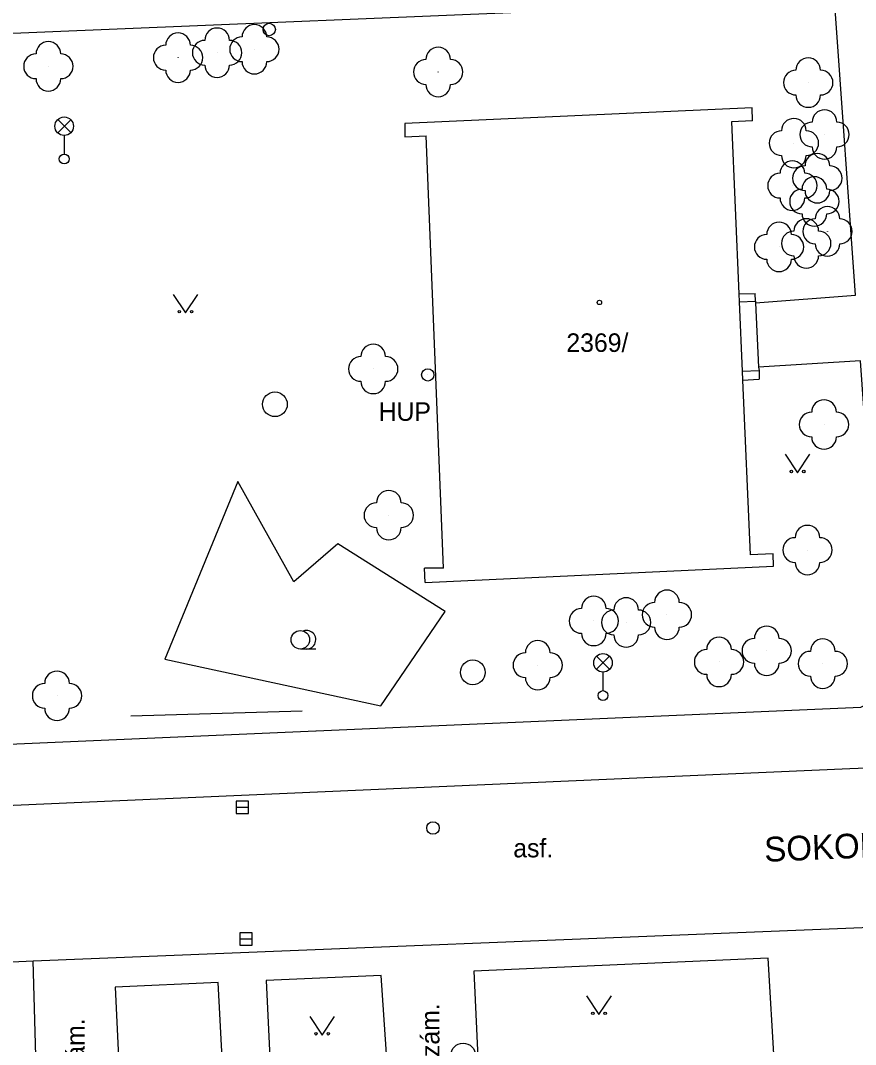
# Model space of a CAD drawing. Extents: x -737812 to -729375, y -1123000 to -1115500.
# Drawn here: x -736536.53 to -736502.72, y -1118316.28 to -1118274.83 of the extents above; entities that cross this region are included whole.
import ezdxf

# ---------------------------------------------------------------- set-up
doc = ezdxf.new("R2010")
doc.units = 0
for name, color, linetype in [('Doplněk polohopisu', 7, 'Continuous'), ('Hranice - ploty_ zdi', 7, 'Continuous'), ('Komunikace', 7, 'Continuous'), ('Názvy ulic_ silnic_ žel_', 7, 'Continuous'), ('Pomocné popisy', 7, 'Continuous'), ('Popisy povr_ zn_ inž_ sítí', 7, 'Continuous'), ('Povr_ zn_ inž_ sítí - el_', 7, 'Continuous'), ('Povr_ zn_ inž_ sítí - kan_', 7, 'Continuous'), ('Povr_ zn_ inž_ sítí - pl_', 7, 'Continuous'), ('Povr_ zn_ inž_ sítí - vod_', 7, 'Continuous'), ('Stavební objekty', 7, 'Continuous'), ('Zeleň', 7, 'Continuous'), ('Značky druhů budov', 7, 'Continuous'), ('Značky druhů pozemků', 7, 'Continuous'), ('Čísla popisná', 7, 'Continuous')]:
    doc.layers.add(name, color=color, linetype=linetype)

msp = doc.modelspace()

# ---------------------------------------------------------------- linework, layer by layer
at = {"layer": 'Doplněk polohopisu'}
for points in [[(-736506.77, -1118286.27), (-736502.73, -1118285.96), (-736503.55, -1118274.38), (-736504, -1118273.98), (-736544.99, -1118275.7), (-736552.63, -1118299.34), (-736546.81, -1118299.16), (-736546.64, -1118304.55)], [(-736546.64, -1118304.55), (-736502.51, -1118302.63), (-736501.87, -1118302.33), (-736501.61, -1118301.65), (-736502.53, -1118288.61), (-736506.65, -1118288.87)], [(-736506.01, -1118317.13), (-736506.26, -1118312.79), (-736518.18, -1118313.31), (-736517.95, -1118318.27)], [(-736528.26, -1118318.86), (-736528.53, -1118313.78), (-736532.69, -1118313.96), (-736532.45, -1118319.06)], [(-736521.62, -1118318.06), (-736521.93, -1118313.49), (-736526.58, -1118313.69), (-736526.34, -1118318.8)]]:
    msp.add_lwpolyline(points, dxfattribs=at)
at = {"layer": 'Hranice - ploty_ zdi'}
for points in [[(-736507.45, -1118285.9), (-736506.79, -1118285.88)], [(-736506.78, -1118286.19), (-736506.79, -1118285.88)], [(-736507.43, -1118286.22), (-736506.78, -1118286.19)], [(-736506.78, -1118286.19), (-736506.77, -1118286.27), (-736506.65, -1118288.87), (-736506.62, -1118289)], [(-736507.31, -1118289.03), (-736506.62, -1118289)], [(-736506.62, -1118289), (-736506.62, -1118289.36)], [(-736507.3, -1118289.39), (-736506.62, -1118289.36)], [(-736525.13, -1118302.79), (-736532.06, -1118303)]]:
    msp.add_lwpolyline(points, dxfattribs=at)
at = {"layer": 'Komunikace'}
for p, q in [((-736536.01, -1118312.9), (-736497.19, -1118311.34)), ((-736591.32, -1118315.35), (-736536.01, -1118312.9)), ((-736535.87, -1118318.46), (-736536.01, -1118312.9))]:
    msp.add_line(p, q, dxfattribs=at)
msp.add_lwpolyline([(-736400.68, -1118302.12), (-736401.85, -1118302.4), (-736402.74, -1118302.47), (-736405.69, -1118302.21), (-736408.34, -1118301.03), (-736412.01, -1118301.15), (-736413.02, -1118301.2), (-736429.04, -1118301.88), (-736430.04, -1118301.95), (-736442.01, -1118302.44), (-736443.03, -1118302.52), (-736478.54, -1118303.97), (-736491.96, -1118304.63), (-736492.94, -1118304.71), (-736501.96, -1118305.09), (-736502.96, -1118305.13), (-736535.58, -1118306.56), (-736558.89, -1118307.58), (-736559.87, -1118307.64), (-736568.86, -1118308.05), (-736569.85, -1118308.09), (-736600.81, -1118309.42)], dxfattribs=at)
at = {"layer": 'Povr_ zn_ inž_ sítí - el_'}
for p, q in [((-736535.024, -1118279.378), (-736534.496, -1118278.85)), ((-736534.488, -1118279.375), (-736535.016, -1118278.846)), ((-736534.76, -1118279.49), (-736534.76, -1118280.24)), ((-736513.214, -1118301.098), (-736512.686, -1118300.57)), ((-736512.678, -1118301.095), (-736513.206, -1118300.566)), ((-736512.95, -1118301.21), (-736512.95, -1118301.96))]:
    msp.add_line(p, q, dxfattribs=at)
for centre, radius in [((-736534.76, -1118279.115), 0.375), ((-736534.76, -1118280.44), 0.2), ((-736512.95, -1118300.835), 0.375), ((-736512.95, -1118302.16), 0.2)]:
    msp.add_circle(centre, radius, dxfattribs=at)
at = {"layer": 'Povr_ zn_ inž_ sítí - kan_'}
for p, q in [((-736527.8, -1118306.68), (-736527.3, -1118306.68)), ((-736527.65, -1118312.01), (-736527.15, -1118312.01))]:
    msp.add_line(p, q, dxfattribs=at)
for points in [[(-736527.8, -1118306.931), (-736527.3, -1118306.931), (-736527.3, -1118306.43), (-736527.8, -1118306.43)], [(-736527.65, -1118312.261), (-736527.15, -1118312.261), (-736527.15, -1118311.76), (-736527.65, -1118311.76)]]:
    msp.add_lwpolyline(points, close=True, dxfattribs=at)
for centre in [(-736526.23, -1118290.37), (-736518.22, -1118301.22), (-736518.61, -1118316.73)]:
    msp.add_circle(centre, 0.5, dxfattribs=at)
at = {"layer": 'Povr_ zn_ inž_ sítí - pl_'}
for radius in [0.25, 0.0005]:
    msp.add_circle((-736520.04, -1118289.181), radius, dxfattribs=at)
at = {"layer": 'Povr_ zn_ inž_ sítí - vod_'}
for centre in [(-736526.46, -1118275.2), (-736519.83, -1118307.52)]:
    msp.add_circle(centre, 0.25, dxfattribs=at)
at = {"layer": 'Stavební objekty'}
for points in [[(-736506.91, -1118278.37), (-736520.97, -1118279.01)], [(-736506.89, -1118278.9), (-736506.91, -1118278.37)], [(-736506.89, -1118278.9), (-736507.75, -1118278.94)], [(-736507.75, -1118278.94), (-736507.45, -1118285.9), (-736507.43, -1118286.22), (-736507.31, -1118289.03), (-736507.3, -1118289.39), (-736506.99, -1118296.46)], [(-736520.97, -1118279.01), (-736520.97, -1118279.54)], [(-736520.97, -1118279.54), (-736520.11, -1118279.5)], [(-736519.4, -1118297.01), (-736520.11, -1118279.5)], [(-736506.06, -1118296.43), (-736506.99, -1118296.46)], [(-736506.04, -1118296.92), (-736506.06, -1118296.43)], [(-736519.4, -1118297.01), (-736520.18, -1118297)], [(-736520.15, -1118297.58), (-736520.18, -1118297)], [(-736520.15, -1118297.58), (-736506.04, -1118296.92)]]:
    msp.add_lwpolyline(points, dxfattribs=at)
at = {"layer": 'Zeleň'}
for points in [[(-736527.73, -1118293.49), (-736530.68, -1118300.69)], [(-736525.46, -1118297.55), (-736527.73, -1118293.49)], [(-736523.68, -1118296.02), (-736525.46, -1118297.55)], [(-736519.34, -1118298.76), (-736523.68, -1118296.02)], [(-736521.94, -1118302.57), (-736519.34, -1118298.76)], [(-736530.68, -1118300.69), (-736521.94, -1118302.57)]]:
    msp.add_lwpolyline(points, dxfattribs=at)
for centre in [(-736527.06, -1118276), (-736530.15, -1118276.34), (-736528.57, -1118276.14), (-736535.4, -1118276.69), (-736519.62, -1118276.92), (-736504.64, -1118277.35), (-736503.98, -1118279.45), (-736505.22, -1118279.8), (-736504.27, -1118281.22), (-736505.28, -1118281.52), (-736504.39, -1118282.16), (-736503.86, -1118283.37), (-736504.72, -1118283.86), (-736505.82, -1118284), (-736522.25, -1118288.94), (-736504, -1118291.19), (-736521.62, -1118294.86), (-736504.67, -1118296.27), (-736513.32, -1118299.14), (-736512.01, -1118299.2), (-736510.36, -1118298.89), (-736506.32, -1118300.35), (-736515.59, -1118300.93), (-736508.25, -1118300.8), (-736504.05, -1118300.87), (-736535.05, -1118302.17)]:
    msp.add_circle(centre, 0.0005, dxfattribs=at)
for centre, start, end in [((-736528.57, -1118275.64), 360, 180), ((-736527.06, -1118275.5), 360, 180), ((-736530.15, -1118275.84), 360, 180), ((-736529.07, -1118276.14), 90, 270), ((-736528.07, -1118276.14), 270, 90), ((-736527.56, -1118276), 90, 270), ((-736526.56, -1118276), 270, 90), ((-736535.4, -1118276.19), 360, 180), ((-736530.65, -1118276.34), 90, 270), ((-736529.65, -1118276.34), 270, 90), ((-736519.62, -1118276.42), 360, 180), ((-736535.9, -1118276.69), 90, 270), ((-736534.9, -1118276.69), 270, 90), ((-736520.12, -1118276.92), 90, 270), ((-736519.12, -1118276.92), 270, 90), ((-736504.64, -1118276.85), 360, 180), ((-736530.15, -1118276.84), 180, 360), ((-736528.57, -1118276.64), 180, 360), ((-736527.06, -1118276.5), 180, 360), ((-736505.14, -1118277.35), 90, 270), ((-736504.14, -1118277.35), 270, 90), ((-736535.4, -1118277.19), 180, 360), ((-736519.62, -1118277.42), 180, 360), ((-736504.64, -1118277.85), 180, 360), ((-736503.98, -1118278.95), 360, 180), ((-736505.22, -1118279.3), 360, 180), ((-736504.48, -1118279.45), 90, 270), ((-736503.48, -1118279.45), 270, 90), ((-736505.72, -1118279.8), 90, 270), ((-736504.72, -1118279.8), 270, 90), ((-736503.98, -1118279.95), 180, 360), ((-736505.28, -1118281.02), 360, 180), ((-736505.22, -1118280.3), 180, 360), ((-736504.27, -1118280.72), 360, 180), ((-736505.78, -1118281.52), 90, 270), ((-736504.77, -1118281.22), 90, 270), ((-736504.78, -1118281.52), 270, 90), ((-736503.77, -1118281.22), 270, 90), ((-736504.39, -1118281.66), 360, 180), ((-736504.89, -1118282.16), 90, 270), ((-736504.27, -1118281.72), 180, 360), ((-736503.89, -1118282.16), 270, 90), ((-736505.28, -1118282.02), 180, 360), ((-736504.39, -1118282.66), 180, 360), ((-736503.86, -1118282.87), 360, 180), ((-736505.82, -1118283.5), 360, 180), ((-736504.72, -1118283.36), 360, 180), ((-736504.36, -1118283.37), 90, 270), ((-736503.36, -1118283.37), 270, 90), ((-736506.32, -1118284), 90, 270), ((-736505.22, -1118283.86), 90, 270), ((-736505.32, -1118284), 270, 90), ((-736504.22, -1118283.86), 270, 90), ((-736503.86, -1118283.87), 180, 360), ((-736505.82, -1118284.5), 180, 360), ((-736504.72, -1118284.36), 180, 360), ((-736522.25, -1118288.44), 360, 180), ((-736522.75, -1118288.94), 90, 270), ((-736521.75, -1118288.94), 270, 90), ((-736522.25, -1118289.44), 180, 360), ((-736504, -1118290.69), 360, 180), ((-736504.5, -1118291.19), 90, 270), ((-736503.5, -1118291.19), 270, 90), ((-736504, -1118291.69), 180, 360), ((-736521.62, -1118294.36), 360, 180), ((-736522.12, -1118294.86), 90, 270), ((-736521.12, -1118294.86), 270, 90), ((-736521.62, -1118295.36), 180, 360), ((-736504.67, -1118295.77), 360, 180), ((-736505.17, -1118296.27), 90, 270), ((-736504.17, -1118296.27), 270, 90), ((-736504.67, -1118296.77), 180, 360), ((-736510.36, -1118298.39), 360, 180), ((-736513.32, -1118298.64), 360, 180), ((-736512.01, -1118298.7), 360, 180), ((-736510.86, -1118298.89), 90, 270), ((-736509.86, -1118298.89), 270, 90), ((-736513.82, -1118299.14), 90, 270), ((-736512.51, -1118299.2), 90, 270), ((-736512.82, -1118299.14), 270, 90), ((-736511.51, -1118299.2), 270, 90), ((-736513.32, -1118299.64), 180, 360), ((-736510.36, -1118299.39), 180, 360), ((-736506.32, -1118299.85), 360, 180), ((-736515.59, -1118300.43), 360, 180), ((-736512.01, -1118299.7), 180, 360), ((-736508.25, -1118300.3), 360, 180), ((-736506.82, -1118300.35), 90, 270), ((-736505.82, -1118300.35), 270, 90), ((-736504.05, -1118300.37), 360, 180), ((-736516.09, -1118300.93), 90, 270), ((-736515.09, -1118300.93), 270, 90), ((-736508.75, -1118300.8), 90, 270), ((-736507.75, -1118300.8), 270, 90), ((-736504.55, -1118300.87), 90, 270), ((-736503.55, -1118300.87), 270, 90), ((-736506.32, -1118300.85), 180, 360), ((-736535.05, -1118301.67), 360, 180), ((-736508.25, -1118301.3), 180, 360), ((-736535.55, -1118302.17), 90, 270), ((-736534.55, -1118302.17), 270, 90), ((-736515.59, -1118301.43), 180, 360), ((-736504.05, -1118301.37), 180, 360), ((-736535.05, -1118302.67), 180, 360)]:
    msp.add_arc(centre, 0.5, start, end, dxfattribs=at)
at = {"layer": 'Značky druhů budov'}
msp.add_circle((-736513.09, -1118286.25), 0.0875, dxfattribs=at)
at = {"layer": 'Značky druhů pozemků'}
msp.add_line((-736525.2, -1118300.275), (-736524.575, -1118300.275), dxfattribs=at)
for points in [[(-736530.35, -1118285.92), (-736529.85, -1118286.67), (-736529.35, -1118285.92)], [(-736505.57, -1118292.39), (-736505.07, -1118293.14), (-736504.57, -1118292.39)], [(-736513.61, -1118314.32), (-736513.11, -1118315.07), (-736512.61, -1118314.32)], [(-736524.82, -1118315.15), (-736524.32, -1118315.9), (-736523.82, -1118315.15)]]:
    msp.add_lwpolyline(points, dxfattribs=at)
for centre, radius in [((-736530.1, -1118286.62), 0.05), ((-736529.6, -1118286.62), 0.05), ((-736505.32, -1118293.09), 0.05), ((-736504.82, -1118293.09), 0.05), ((-736525.2, -1118299.901), 0.375), ((-736513.36, -1118315.02), 0.05), ((-736512.86, -1118315.02), 0.05), ((-736524.57, -1118315.85), 0.05), ((-736524.07, -1118315.85), 0.05)]:
    msp.add_circle(centre, radius, dxfattribs=at)
msp.add_arc((-736524.95, -1118299.901), 0.375, 249.4944, 109.0474, dxfattribs=at)

# ---------------------------------------------------------------- texts
at = {"layer": 'Názvy ulic_ silnic_ žel_'}
msp.add_text('SOKOLOVSKÁ', height=1, rotation=2.3355, dxfattribs=at).set_placement((-736506.4, -1118308.89))
at = {"layer": 'Pomocné popisy'}
msp.add_text('asf.', height=0.75, dxfattribs=at).set_placement((-736516.58, -1118308.71))
for p in [(-736519.57, -1118316.79), (-736533.93, -1118317.4)]:
    msp.add_text('zám.', height=0.75, rotation=90, dxfattribs=at).set_placement(p)
at = {"layer": 'Popisy povr_ zn_ inž_ sítí'}
msp.add_text('HUP', height=0.75, dxfattribs=at).set_placement((-736522.03, -1118291.04))
at = {"layer": 'Čísla popisná'}
msp.add_text('2369/', height=0.75, dxfattribs=at).set_placement((-736514.43, -1118288.25))

doc.saveas('drawing.dxf')
